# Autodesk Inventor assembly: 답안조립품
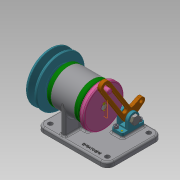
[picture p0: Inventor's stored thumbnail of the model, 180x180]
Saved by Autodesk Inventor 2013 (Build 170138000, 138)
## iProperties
Created: 2019-09
Part Number: 답안조립품
Document SubType Name: Assembly
Designer: Administrator
Author: Administrator
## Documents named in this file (19)
- C:\Users\Administrator\Desktop\390904V1009\답안조립품.iam
- C:\Users\Administrator\Desktop\390904V1009\본체.ipt
- C:\Users\Administrator\Desktop\390904V1009\V-벨트풀리.ipt
- C:\Users\Administrator\Desktop\390904V1009\너트 M8.ipt
- C:\Users\Administrator\Desktop\390904V1009\너트 M10x1.ipt
- C:\Users\Administrator\Desktop\390904V1009\돌림판.ipt
- C:\Users\Administrator\Desktop\390904V1009\멈춤나사 M3x5.ipt
- C:\Users\Administrator\Desktop\390904V1009\베어링 6004.ipt
- C:\Users\Administrator\Desktop\390904V1009\볼트 M4.ipt
- C:\Users\Administrator\Desktop\390904V1009\오일 실 17 30 5.ipt
- C:\Users\Administrator\Desktop\390904V1009\와셔 8x15.5.ipt
- C:\Users\Administrator\Desktop\390904V1009\축.ipt
- C:\Users\Administrator\Desktop\390904V1009\커버.ipt
- C:\Users\Administrator\Desktop\390904V1009\크랭크.ipt
- C:\Users\Administrator\Desktop\390904V1009\키 4 x 4 x 8.ipt
- C:\Users\Administrator\Desktop\390904V1009\키 5 x 5 x 12.ipt
- C:\Users\Administrator\Desktop\390904V1009\핀 3 x 8.ipt
- C:\Users\Administrator\Desktop\390904V1009\힌지 축.ipt
- C:\Users\Administrator\Desktop\390904V1009\힌지.ipt
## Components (3 placed, 2 different names)
1. V-벨트풀리:1
2. 핀 3 x 8:1 — 플러쉬:4
3. 핀 3 x 8:2 — 플러쉬:3
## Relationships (2: Flush 2)
- 플러쉬:3 [Flush]: 핀 3 x 8:2
- 플러쉬:4 [Flush]: 핀 3 x 8:1
